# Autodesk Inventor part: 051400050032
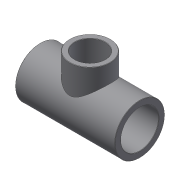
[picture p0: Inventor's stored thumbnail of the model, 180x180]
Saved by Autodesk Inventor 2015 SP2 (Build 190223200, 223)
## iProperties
Created: 2017-10
Part Number: 051400050032
Material: Generic
Description: PLASSON REDUCER TEE - CEMENT PVC 50-32-50
Document SubType Name: Modeling
Designer: KIM
Density: 1 g/cm^3
Appearance: Default
Author: KIM
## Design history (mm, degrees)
derived "051400.ipt"
feature "Solid1::051400.ipt"
feature "Solid2::051400.ipt"
tag "TaggingFeature1"
body "Solid1"
other parameters: "d0" = 118, "d1" = 61, "d2" = 31, "d5" = 45, "d7" = 0.5, "d8" = 31, "d9" = 49.5, "d10" = 41, "d11" = 32, "d12" = 28.8, "d23" = 22, "d24" = 0.5, "d26" = 0, "d30" = 0, "d32" = 0, "E_" = 61, "H_" = 118, "l_" = 31, "Z_" = 14, "E_1" = 41, "l_1" = 22, "Z_1" = 12.5, "d_1" = 32
